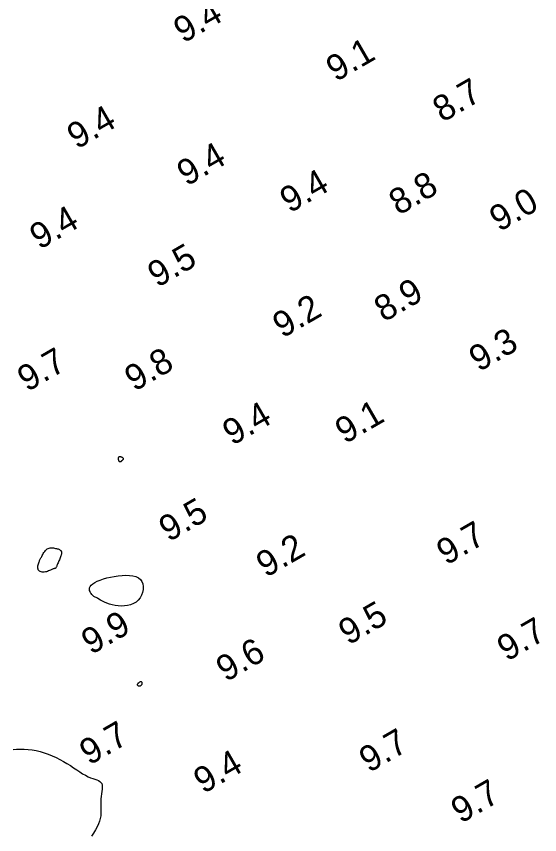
# Model space of a CAD drawing. Extents: x 3024098 to 3056816, y 418252 to 509144.
# Drawn here: x 3033219 to 3033321, y 418785.7 to 418945.4 of the extents above; entities that cross this region are included whole.
import ezdxf

# ---------------------------------------------------------------- set-up
doc = ezdxf.new("R2010")
doc.units = 0
doc.layers.add('V-CHAN-CONT-EL10', color=7, linetype='Continuous')
doc.layers.add('V-TOPO-SOUN-0911', color=7, linetype='Continuous')

msp = doc.modelspace()

# ---------------------------------------------------------------- linework, layer by layer
at = {"layer": 'V-CHAN-CONT-EL10'}
for points in [[(3033238.92, 418858.84), (3033238.9, 418858.9), (3033238.89, 418858.96), (3033238.88, 418859.01), (3033238.88, 418859.07), (3033238.88, 418859.12), (3033238.88, 418859.17), (3033238.89, 418859.21), (3033238.9, 418859.26), (3033238.91, 418859.3), (3033238.93, 418859.34), (3033238.95, 418859.37), (3033238.97, 418859.4), (3033239, 418859.43), (3033239.04, 418859.45), (3033239.09, 418859.46), (3033239.14, 418859.47), (3033239.19, 418859.47), (3033239.25, 418859.46), (3033239.32, 418859.45), (3033239.38, 418859.43), (3033239.44, 418859.41), (3033239.51, 418859.38), (3033239.57, 418859.35), (3033239.62, 418859.31), (3033239.67, 418859.27), (3033239.71, 418859.22), (3033239.75, 418859.17), (3033239.78, 418859.13), (3033239.8, 418859.08), (3033239.81, 418859.03), (3033239.82, 418858.99), (3033239.81, 418858.95), (3033239.8, 418858.91), (3033239.77, 418858.88), (3033239.75, 418858.85), (3033239.71, 418858.81), (3033239.67, 418858.77), (3033239.63, 418858.73), (3033239.58, 418858.69), (3033239.54, 418858.64), (3033239.49, 418858.59), (3033239.44, 418858.54), (3033239.39, 418858.49), (3033239.34, 418858.45), (3033239.29, 418858.42), (3033239.24, 418858.4), (3033239.2, 418858.39), (3033239.15, 418858.41), (3033239.11, 418858.43), (3033239.08, 418858.47), (3033239.04, 418858.52), (3033239.01, 418858.58), (3033238.98, 418858.64), (3033238.96, 418858.71), (3033238.93, 418858.77)], [(3033225.92, 418837.44), (3033225.77, 418837.37), (3033225.61, 418837.29), (3033225.43, 418837.21), (3033225.24, 418837.12), (3033225.05, 418837.05), (3033224.84, 418836.98), (3033224.63, 418836.93), (3033224.42, 418836.9), (3033224.21, 418836.89), (3033224, 418836.9), (3033223.81, 418836.94), (3033223.64, 418837), (3033223.48, 418837.09), (3033223.35, 418837.2), (3033223.26, 418837.34), (3033223.2, 418837.5), (3033223.17, 418837.69), (3033223.17, 418837.89), (3033223.19, 418838.1), (3033223.23, 418838.31), (3033223.28, 418838.52), (3033223.34, 418838.71), (3033223.4, 418838.89), (3033223.46, 418839.04), (3033223.52, 418839.18), (3033223.58, 418839.3), (3033223.64, 418839.42), (3033223.7, 418839.53), (3033223.77, 418839.66), (3033223.85, 418839.79), (3033223.93, 418839.95), (3033224.02, 418840.13), (3033224.12, 418840.32), (3033224.23, 418840.53), (3033224.36, 418840.73), (3033224.5, 418840.93), (3033224.65, 418841.12), (3033224.81, 418841.28), (3033224.99, 418841.42), (3033225.18, 418841.52), (3033225.38, 418841.59), (3033225.59, 418841.62), (3033225.81, 418841.64), (3033226.02, 418841.63), (3033226.23, 418841.61), (3033226.43, 418841.58), (3033226.62, 418841.54), (3033226.8, 418841.5), (3033226.96, 418841.46), (3033227.11, 418841.42), (3033227.24, 418841.37), (3033227.36, 418841.32), (3033227.46, 418841.27), (3033227.54, 418841.21), (3033227.61, 418841.15), (3033227.67, 418841.09), (3033227.71, 418841.03), (3033227.74, 418840.96), (3033227.76, 418840.9), (3033227.77, 418840.83), (3033227.78, 418840.77), (3033227.78, 418840.71), (3033227.78, 418840.66), (3033227.78, 418840.61), (3033227.78, 418840.56), (3033227.78, 418840.51), (3033227.77, 418840.45), (3033227.75, 418840.38), (3033227.73, 418840.29), (3033227.69, 418840.18), (3033227.64, 418840.05), (3033227.59, 418839.9), (3033227.52, 418839.72), (3033227.44, 418839.52), (3033227.36, 418839.32), (3033227.27, 418839.1), (3033227.19, 418838.9), (3033227.11, 418838.69), (3033227.03, 418838.51), (3033226.96, 418838.34), (3033226.9, 418838.19), (3033226.84, 418838.05), (3033226.79, 418837.94), (3033226.75, 418837.85), (3033226.7, 418837.77), (3033226.66, 418837.7), (3033226.61, 418837.66), (3033226.57, 418837.63), (3033226.52, 418837.61), (3033226.47, 418837.6), (3033226.41, 418837.59), (3033226.34, 418837.58), (3033226.26, 418837.56), (3033226.16, 418837.54), (3033226.05, 418837.5)], [(3033233.87, 418834.63), (3033234.27, 418834.88), (3033234.76, 418835.12), (3033235.33, 418835.35), (3033235.95, 418835.56), (3033236.63, 418835.76), (3033237.34, 418835.92), (3033238.08, 418836.07), (3033238.84, 418836.18), (3033239.59, 418836.26), (3033240.33, 418836.29), (3033241.03, 418836.27), (3033241.68, 418836.19), (3033242.26, 418836.04), (3033242.77, 418835.81), (3033243.17, 418835.49), (3033243.47, 418835.08), (3033243.65, 418834.6), (3033243.73, 418834.07), (3033243.72, 418833.51), (3033243.6, 418832.95), (3033243.4, 418832.4), (3033243.12, 418831.89), (3033242.75, 418831.43), (3033242.31, 418831.06), (3033241.81, 418830.76), (3033241.25, 418830.54), (3033240.67, 418830.39), (3033240.06, 418830.3), (3033239.44, 418830.27), (3033238.82, 418830.29), (3033238.23, 418830.37), (3033237.66, 418830.49), (3033237.12, 418830.65), (3033236.63, 418830.84), (3033236.17, 418831.04), (3033235.75, 418831.24), (3033235.38, 418831.45), (3033235.05, 418831.63), (3033234.78, 418831.79), (3033234.55, 418831.92), (3033234.37, 418832.02), (3033234.23, 418832.1), (3033234.1, 418832.17), (3033234, 418832.24), (3033233.9, 418832.32), (3033233.81, 418832.42), (3033233.7, 418832.54), (3033233.58, 418832.7), (3033233.45, 418832.89), (3033233.34, 418833.1), (3033233.26, 418833.33), (3033233.23, 418833.58), (3033233.25, 418833.84), (3033233.36, 418834.11), (3033233.56, 418834.37)], [(3033242.76, 418815.26), (3033242.83, 418815.32), (3033242.91, 418815.39), (3033242.99, 418815.44), (3033243.08, 418815.49), (3033243.16, 418815.52), (3033243.24, 418815.54), (3033243.31, 418815.54), (3033243.37, 418815.51), (3033243.41, 418815.47), (3033243.44, 418815.41), (3033243.46, 418815.34), (3033243.47, 418815.27), (3033243.47, 418815.19), (3033243.46, 418815.1), (3033243.44, 418815.03), (3033243.42, 418814.95), (3033243.38, 418814.89), (3033243.34, 418814.83), (3033243.3, 418814.78), (3033243.25, 418814.74), (3033243.19, 418814.7), (3033243.14, 418814.67), (3033243.08, 418814.66), (3033243.02, 418814.64), (3033242.96, 418814.64), (3033242.9, 418814.65), (3033242.85, 418814.66), (3033242.8, 418814.67), (3033242.75, 418814.7), (3033242.7, 418814.73), (3033242.67, 418814.76), (3033242.64, 418814.8), (3033242.61, 418814.85), (3033242.6, 418814.89), (3033242.59, 418814.95), (3033242.6, 418815), (3033242.62, 418815.06), (3033242.65, 418815.12), (3033242.7, 418815.19)]]:
    msp.add_lwpolyline(points, close=True, dxfattribs=at)
msp.add_lwpolyline([(3033218.33, 418802.31), (3033219.04, 418802.35), (3033219.77, 418802.37), (3033220.52, 418802.36), (3033221.29, 418802.31), (3033222.06, 418802.22), (3033222.85, 418802.08), (3033223.63, 418801.89), (3033224.41, 418801.66), (3033225.19, 418801.38), (3033225.96, 418801.07), (3033226.71, 418800.73), (3033227.45, 418800.36), (3033228.16, 418799.96), (3033228.85, 418799.55), (3033229.51, 418799.13), (3033230.15, 418798.71), (3033230.76, 418798.3), (3033231.34, 418797.92), (3033231.9, 418797.56), (3033232.44, 418797.24), (3033232.95, 418796.97), (3033233.43, 418796.76), (3033233.88, 418796.6), (3033234.29, 418796.46), (3033234.66, 418796.33), (3033234.99, 418796.2), (3033235.26, 418796.04), (3033235.47, 418795.86), (3033235.62, 418795.62), (3033235.71, 418795.31), (3033235.73, 418794.95), (3033235.72, 418794.54), (3033235.67, 418794.09), (3033235.61, 418793.62), (3033235.54, 418793.13), (3033235.48, 418792.64), (3033235.44, 418792.15), (3033235.43, 418791.67), (3033235.44, 418791.2), (3033235.46, 418790.74), (3033235.47, 418790.28), (3033235.46, 418789.81), (3033235.43, 418789.32), (3033235.34, 418788.82), (3033235.2, 418788.29), (3033234.99, 418787.74), (3033234.72, 418787.16), (3033234.4, 418786.57), (3033234.05, 418785.98), (3033233.66, 418785.39)], dxfattribs=at)

# ---------------------------------------------------------------- texts
at = {"layer": 'V-TOPO-SOUN-0911'}
for s, p in [('9.4', (3033251.53, 418940.04)), ('9.1', (3033281.27, 418932.51)), ('8.7', (3033302.05, 418924.59)), ('9.4', (3033230.76, 418919.34)), ('9.4', (3033252.19, 418912.12)), ('9.4', (3033272.26, 418906.87)), ('8.8', (3033293.52, 418906.44)), ('9.0', (3033313.13, 418903.23)), ('9.4', (3033223.48, 418899.75)), ('9.5', (3033246.47, 418892.34)), ('8.9', (3033290.64, 418885.61)), ('9.2', (3033270.85, 418882.46)), ('9.3', (3033309.14, 418875.9)), ('9.7', (3033221.08, 418872)), ('9.8', (3033241.98, 418872.06)), ('9.4', (3033261.08, 418861.5)), ('9.1', (3033283.04, 418861.84)), ('9.5', (3033248.67, 418842.7)), ('9.7', (3033302.81, 418838.14)), ('9.2', (3033267.64, 418835.74)), ('9.5', (3033283.7, 418822.55)), ('9.9', (3033233.55, 418820.68)), ('9.7', (3033314.62, 418819.37)), ('9.6', (3033259.83, 418815.37)), ('9.7', (3033233.19, 418799.1)), ('9.7', (3033287.72, 418797.65)), ('9.4', (3033255.43, 418793.55)), ('9.7', (3033305.63, 418787.74))]:
    msp.add_text(s, height=5, rotation=30, dxfattribs=at).set_placement(p)

doc.saveas('drawing.dxf')
